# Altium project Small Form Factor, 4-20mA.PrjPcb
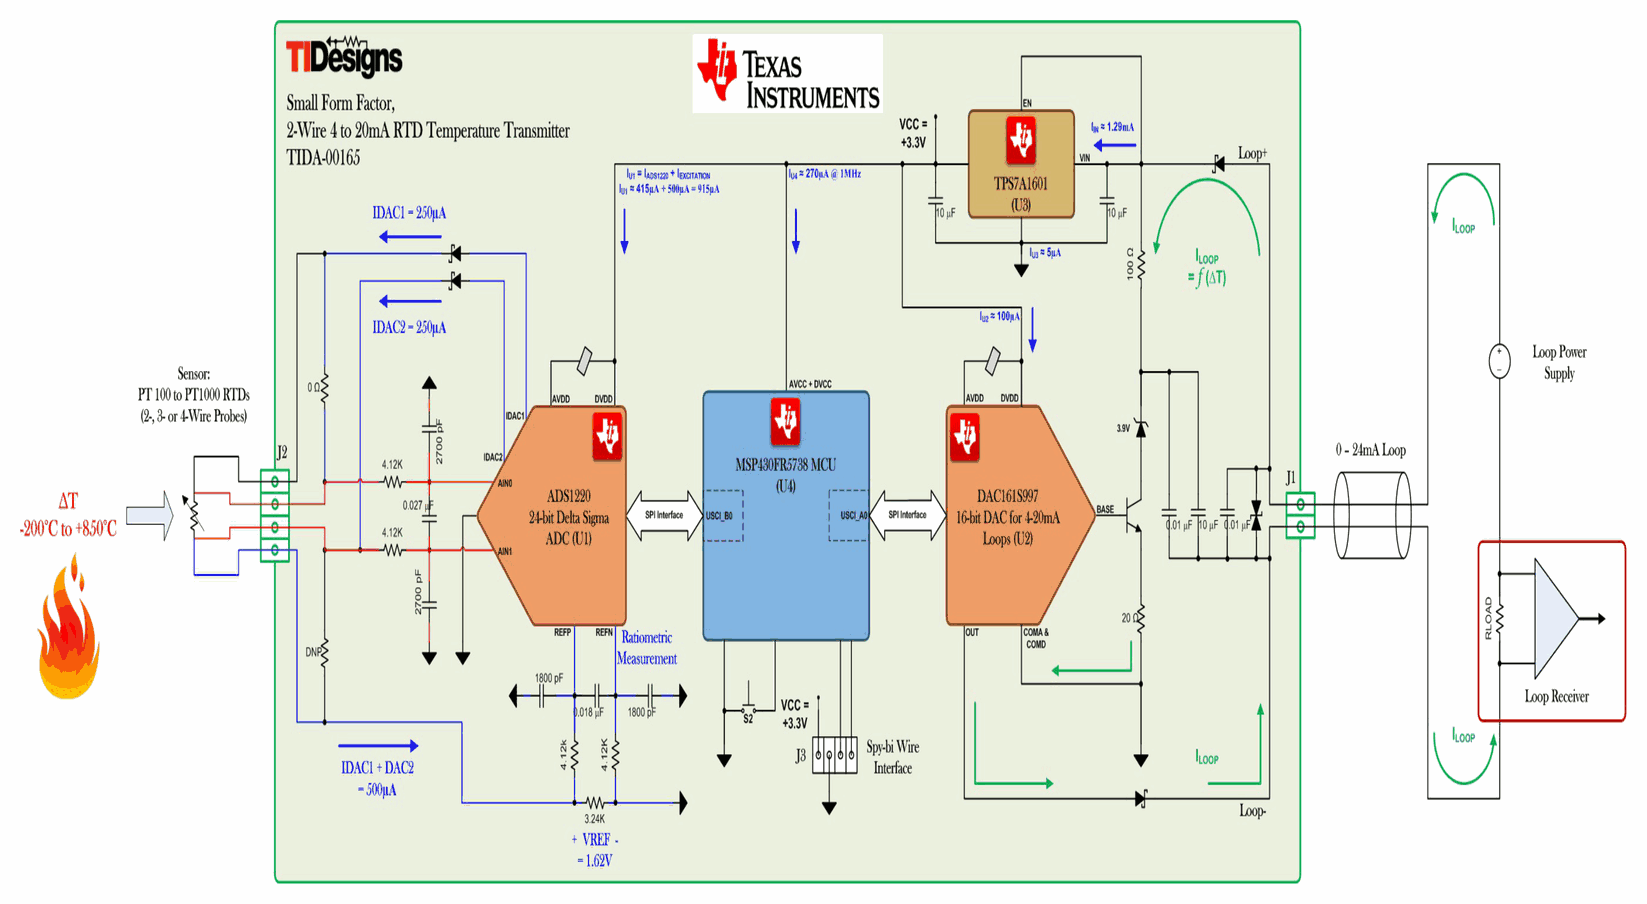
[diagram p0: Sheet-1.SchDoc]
CopyrightYear: 2014; PCB_Layout: Who did the Layout?; PCB_Rev: E1; PRJ_Customer: Public Release; PRJ_Engineer: Sharad Yadav; PRJ_Number: TIDA-00165; PRJ_Title: Small Form Factor 4-20mA Temperature Transmitter; SCH_Rev: E1; TechSupport: http://www.ti.com/support
4 sheets, 68 parts. Net scope: global (net labels, ports and power ports of the same name join across sheets).
Board file: TIDA-00165.PcbDoc
Sheets:
  Sheet-1.SchDoc
  Sheet-2.SchDoc
  Sheet-3.SchDoc
  Sheet-4.SchDoc

## Sheet Sheet-1.SchDoc
size 431 x 279 mm; Date: Not shown in title block; ApprovedBy: Not shown in title block; CheckedBy: Not shown in title block; Author: Not shown in title block; CompanyName: Not shown in title block; Engineer: Not shown in title block; Organization: Not shown in title block; Address1: Not shown in title block; Address2: Not shown in title block; Address3: Not shown in title block; Address4: Not shown in title block; DocumentNumber: 1; Revision: Use project parameter SCH_Rev; SheetNumber: 1; SheetTotal: 4; PageSetup: Record=PageOptions|CenterHorizontal=True|CenterVertical=True|PrintScale=1.00|XCorrection=1.00|YCorrection=1.00|PrintKind=0|BorderSize=5000000|LeftOffset=0|BottomOffset=0|Orientation=2|PaperLength=1000|PaperWidth=1000|Scale=100|PaperSource=15|PrintQuality=600|MediaType=1|DitherType=10|PaperKind=Letter|PrintScaleMode=1

## Sheet Sheet-2.SchDoc
size 431 x 279 mm; Date: Not shown in title block; ApprovedBy: Not shown in title block; CheckedBy: Not shown in title block; Author: Not shown in title block; CompanyName: Not shown in title block; Engineer: Not shown in title block; Organization: Not shown in title block; Address1: Not shown in title block; Address2: Not shown in title block; Address3: Not shown in title block; Address4: Not shown in title block; DocumentNumber: 2; Revision: Use project parameter SCH_Rev; SheetNumber: 2; SheetTotal: 4; PageSetup: Record=PageOptions|CenterHorizontal=True|CenterVertical=True|PrintScale=1.00|XCorrection=1.00|YCorrection=1.00|PrintKind=0|BorderSize=5000000|LeftOffset=0|BottomOffset=0|Orientation=2|PaperLength=1000|PaperWidth=1000|Scale=100|PaperSource=15|PrintQuality=600|MediaType=1|DitherType=10|PaperKind=Letter|PrintScaleMode=1
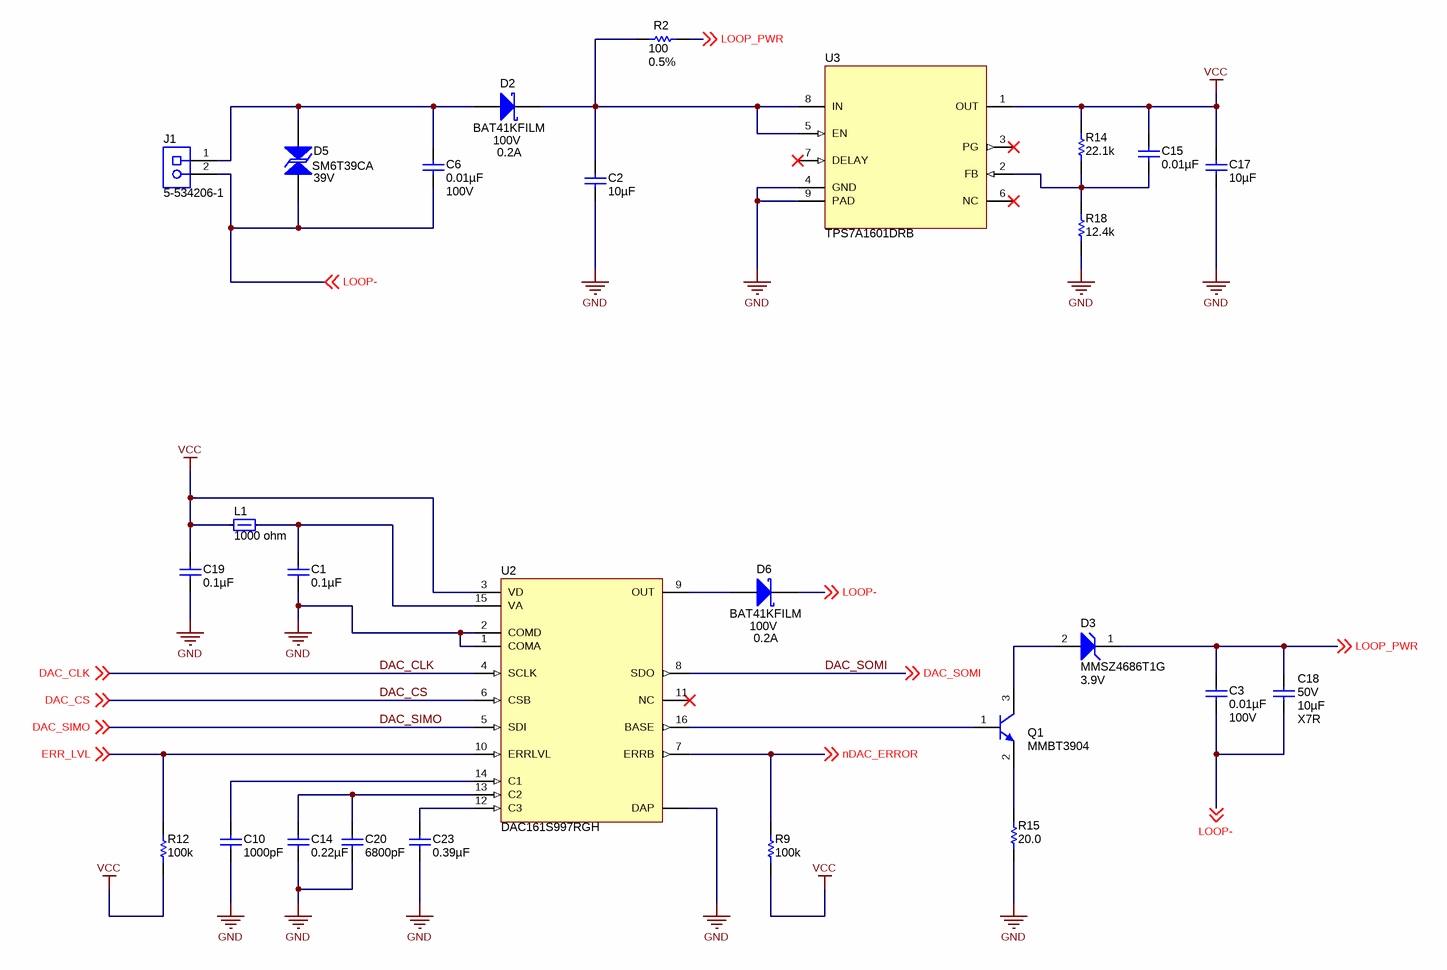
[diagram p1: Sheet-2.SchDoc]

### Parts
C1  ValueDisplayed: 0.1µF  [0402]  (hidden comment: C1005X5R0J104K)
C2  ValueDisplayed: 10µF  [1210]  (hidden comment: GRM32ER71H106KA12L)
C3  ValueDisplayed: 0.01µF  Value2: 100V  [0603]  (hidden comment: C1608X7R2A103K)
C6  ValueDisplayed: 0.01µF  Value2: 100V  [0603]  (hidden comment: C1608X7R2A103K)
C10  ValueDisplayed: 1000pF  [0402]  (hidden comment: GRM155R60J102KA01D)
C14  ValueDisplayed: 0.22µF  [0402]  (hidden comment: GRM155R60J224KE01D)
C15  ValueDisplayed: 0.01µF  [0402]  (hidden comment: GRM155R70J103KA01D)
C17  ValueDisplayed: 10µF  [0805_HV]  (hidden comment: GRM21BR70J106KE76L)
C18  ValueDisplayed: 10µF  Value2: 50V  TempCo: X7R  [1210]  (hidden comment: GRM32ER71H106KA12L)
C19  ValueDisplayed: 0.1µF  [0402]  (hidden comment: C1005X5R0J104K)
C20  ValueDisplayed: 6800pF  [0402]  (hidden comment: GRM155R71E682KA01D)
C23  ValueDisplayed: 0.39µF  [0402]  (hidden comment: GRM155R61A394KE15D)
D2  BAT41KFILM  value 100V  Value1: 0.2A  [SOD-523]
D3  MMSZ4686T1G  value 3.9V  [SOD-123]
D5  value 39V  [SMB]  (hidden comment: SM6T39CA)
D6  BAT41KFILM  value 100V  Value1: 0.2A  [SOD-523]
J1  5-534206-1  [CONN_534206-1]
L1  value 1000 ohm  [0402]  (hidden comment: BLM15HG102SN1D)
Q1  MMBT3904  [SOT-23]
R2  value 100  Value1: 0.5%  [0603]  (hidden comment: RT0603DRE07100RL)
R9  value 100k  [0402]  (hidden comment: CRCW0402100KJNED)
R12  value 100k  [0402]  (hidden comment: CRCW0402100KJNED)
R14  value 22.1k  [0402]  (hidden comment: CRCW040222K1FKED)
R15  value 20.0  [0402]  (hidden comment: CRCW040220R0FKED)
R18  value 12.4k  [0402]  (hidden comment: CRCW040212K4FKED)
U2  DAC161S997RGH  [RGH0016A]
U3  TPS7A1601DRB  [DRB0008A]

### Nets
GND: C1.2 C2.2 C10.2 C14.2 C17.2 C19.2 C20.2 C23.2 R15.2 R18.1 U2.1(COMA) U2.2(COMD) U2.17(DAP) U3.4(GND) U3.9(PAD)
VCC: C15.1 C17.1 C19.1 L1.1 R9.1 R12.2 R14.2 U2.3(VD) U3.1(OUT)
DAC_CLK: U2.4(SCLK) ; off-sheet DAC_CLK
DAC_CS: U2.6(CSB) ; off-sheet DAC_CS
DAC_SIMO: U2.5(SDI) ; off-sheet DAC_SIMO
DAC_SOMI: U2.8(SDO) ; off-sheet DAC_SOMI
ERR_LVL: R12.1 U2.10(ERRLVL) ; off-sheet ERR_LVL
LOOP-: C3.2 C6.2 C18.2 D5.2 D6.1(K) J1.2 ; off-sheet LOOP-
LOOP_PWR: C3.1 C18.1 D3.1(K) R2.2 ; off-sheet LOOP_PWR
nDAC_ERROR: R9.2 U2.7(ERRB) ; off-sheet nDAC_ERROR
NetC1_1: C1.1 L1.2 U2.15(VA)
NetC2_1: C2.1 D2.1(K) R2.1 U3.5(EN) U3.8(IN)
NetC6_1: C6.1 D2.2(A) D5.1 J1.1
NetC10_1: C10.1 U2.14(C1)
NetC14_1: C14.1 C20.1 U2.13(C2)
NetC15_2: C15.2 R14.1 R18.2 U3.2(FB)
NetC23_1: C23.1 U2.12(C3)
NetD3_2: D3.2(A) Q1.3(C)
NetD6_2: D6.2(A) U2.9(OUT)
NetQ1_1: Q1.1(B) U2.16(BASE)
NetQ1_2: Q1.2(E) R15.1

Not connected (* = marked no-connect by the designer): U2 11(NC)*; U3 3(PG)* 6(NC)* 7(DELAY)*

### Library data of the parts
C1 C19 = C1005X5R0J104K: CAP, CERM, 0.1uF, 6.3V, +/-10%, X5R, 0402; Manufacturer: TDK; Polarized: N; CompType: Capacitor; U/M: EA; Cap_F: 0.0000001; Tolerance_%: 10; ESR_Ohm: 0.0186; Value1: 0.0186 ohm; VDC_V: 6.3; TaMin_C: -55; TaMax_C: 85
C2 C18 = GRM32ER71H106KA12L: CAP, CERM, 10uF, 50V, +/-10%, X7R, 1210; Manufacturer: MuRata; Polarized: N; CompType: Capacitor; U/M: EA; Cap_F: 0.00001; Tolerance_%: 10; Value1: Unknown; VDC_V: 50; TaMin_C: -55; TaMax_C: 125
C3 C6 = C1608X7R2A103K: CAP, CERM, 0.01uF, 100V, +/-10%, X7R, 0603; Manufacturer: TDK; Polarized: N; CompType: Capacitor; U/M: EA; Cap_F: 0.00000001; Tolerance_%: 10; ESR_Ohm: 0.0661; Value1: 0.0661 ohm; VDC_V: 100; TaMin_C: -55; TaMax_C: 125
C10 = GRM155R60J102KA01D: CAP, CERM, 1000pF, 6.3V, +/-10%, X5R, 0402; Manufacturer: MuRata; Polarized: N; CompType: Capacitor; U/M: EA; Cap_F: 0.000000001; Tolerance_%: 10; Value1: Unknown; VDC_V: 6.3; TaMin_C: -55; TaMax_C: 85
C14 = GRM155R60J224KE01D: CAP, CERM, 0.22uF, 6.3V, +/-10%, X5R, 0402; Manufacturer: MuRata; Polarized: N; CompType: Capacitor; U/M: EA; Cap_F: 0.00000022; Tolerance_%: 10; Value1: Unknown; VDC_V: 6.3; TaMin_C: -55; TaMax_C: 85
C15 = GRM155R70J103KA01D: CAP, CERM, 0.01uF, 6.3V, +/-10%, X7R, 0402; Manufacturer: MuRata; Polarized: N; CompType: Capacitor; U/M: EA; Cap_F: 0.00000001; Tolerance_%: 10; Value1: Unknown; VDC_V: 6.3; TaMin_C: -55; TaMax_C: 125
C17 = GRM21BR70J106KE76L: CAP, CERM, 10uF, 6.3V, +/-10%, X7R, 0805; Manufacturer: MuRata; Polarized: N; CompType: Capacitor; U/M: EA; Cap_F: 0.00001; Tolerance_%: 10; Value1: Unknown; VDC_V: 6.3; TaMin_C: -55; TaMax_C: 125; Cap_Case: 0805
C20 = GRM155R71E682KA01D: CAP, CERM, 6800pF, 25V, +/-10%, X7R, 0402; Manufacturer: MuRata; Polarized: N; CompType: Capacitor; U/M: EA; Cap_F: 0.0000000068; Tolerance_%: 10; Value1: Unknown; VDC_V: 25; TaMin_C: -55; TaMax_C: 125
C23 = GRM155R61A394KE15D: CAP, CERM, 0.39uF, 10V, +/-10%, X5R, 0402; Manufacturer: MuRata; Polarized: N; CompType: Capacitor; U/M: EA; Cap_F: 0.00000039; Tolerance_%: 10; Value1: Unknown; TaMin_C: -55; TaMax_C: 85
D2 D6 = BAT41ZFILM: DIODE SCHOTTKY 100V 0.2A SOD523; Manufacturer: ST Microelectronics; U/M: EA; Vf_V: 1; Value2: 1V; Io_A: 0.2; Vr_V: 100; TJmax_C: 150
D3 = MMSZ4686T1G: Diode, Zener, 3.9V, 500mW, SOD-123; Manufacturer: ON Semiconductor; U/M: EA; Power_W: 0.5; Vz_V: 3.9; Value1: 0.5W; RJA_CperW: 340
D5 = SMBJ40CA-13-F: TVS DIODE 33.3VWM 69.7VC SMB; Manufacturer: STMicroelectronics; U/M: EA; Power_W: 600; Value1: 600W
J1 = 5-534206-1: Connector, Receptacle, 100mil, 2x1, Gold plated, TH; Manufacturer: TE Connectivity; SymbolCreator: a0412235; U/M: EA
L1 = BLM15HG102SN1D: 0.25A Ferrite Bead, 1000 ohm @ 100MHz, SMD; Manufacturer: MuRata; Imax_A: 0.25; Irms: 0.25A @ C rise; Isat: 0.25A @ % inductance drop; DCR_ohm: 1.1; Value1: 1.1 ohm; ZTyp@100MHz_Ohm: 1000; U/M: EA
Q1 = MMBT3904, Fairchild Semiconductor: Transistor, NPN, 40V, 0.2A, SOT-23; CompType: BJT; PNP: 0; NPN: 1; Vceo_V: 40; Vcesat1_V: 0.2; Value: 0.2V; HfeMax: 300; TaMin_C: -55; TaMax_C: 150; U/M: EA
R2 = RT0603DRE07100RL: RES, 100 ohm, 0.5%, 0.1W, 0603; Manufacturer: Yageo America; CompType: Resistor; Value_Code: 100R; Tolerance_%: 0.5; Power_W: 0.1; VDC_V: 75; TempCo: 50 ppm/C; EIA_Code: E192; U/M: EA
R9 R12 = CRCW0402100KJNED: RES, 100k ohm, 5%, 0.063W, 0402; Manufacturer: Vishay-Dale; CompType: Resistor; Res_ohm: 100000; Tolerance_%: 5; Power_W: 0.063; VDC_V: 50; TempCo: 200 ppm/C; EIA_Code: E24; U/M: EA
R14 = CRCW040222K1FKED: RES, 22.1k ohm, 1%, 0.063W, 0402; Manufacturer: Vishay-Dale; CompType: Resistor; Res_ohm: 22100; Value_Code: 22k1; Tolerance_%: 1; Power_W: 0.063; VDC_V: 50; TempCo: 100 ppm/C; EIA_Code: E96; U/M: EA
R15 = CRCW040220R0FKED: RES, 20.0 ohm, 1%, 0.063W, 0402; Manufacturer: Vishay-Dale; CompType: Resistor; Res_ohm: 20; Value_Code: 20R0; Tolerance_%: 1; Power_W: 0.063; VDC_V: 50; TempCo: 100 ppm/C; EIA_Code: E96; U/M: EA
R18 = CRCW040212K4FKED: RES, 12.4k ohm, 1%, 0.063W, 0402; Manufacturer: Vishay-Dale; CompType: Resistor; Res_ohm: 12400; Value_Code: 12k4; Tolerance_%: 1; Power_W: 0.063; VDC_V: 50; TempCo: 100 ppm/C; EIA_Code: E96; U/M: EA
U2 = DAC161S997RGH: 16-bit SPI Programmable DAC for 4-20mA Loops, RGH0016A; Alternate Manufacturer: None; Manufacturer: Texas Instruments; SymbolCreator: x0208325; CompType: IC; U/M: EA
U3 = TPS7A1601DRB: 60-V, 5-µA IQ, 100-mA, Low-Dropout Voltage Regulator with Enable and Power-Good, DRB0008A; Alternate Manufacturer: None; Manufacturer: Texas Instruments; SymbolCreator: a0411947; CompType: IC; U/M: EA

## Sheet Sheet-3.SchDoc
size 431 x 279 mm; Date: Not shown in title block; ApprovedBy: Not shown in title block; CheckedBy: Not shown in title block; Author: Not shown in title block; CompanyName: Not shown in title block; Engineer: Not shown in title block; Organization: Not shown in title block; Address1: Not shown in title block; Address2: Not shown in title block; Address3: Not shown in title block; Address4: Not shown in title block; DocumentNumber: 3; Revision: Use project parameter SCH_Rev; SheetNumber: 3; SheetTotal: 4; PageSetup: Record=PageOptions|CenterHorizontal=True|CenterVertical=True|PrintScale=1.00|XCorrection=1.00|YCorrection=1.00|PrintKind=0|BorderSize=5000000|LeftOffset=0|BottomOffset=0|Orientation=2|PaperLength=1000|PaperWidth=1000|Scale=100|PaperSource=15|PrintQuality=600|MediaType=1|DitherType=10|PaperKind=Letter|PrintScaleMode=1
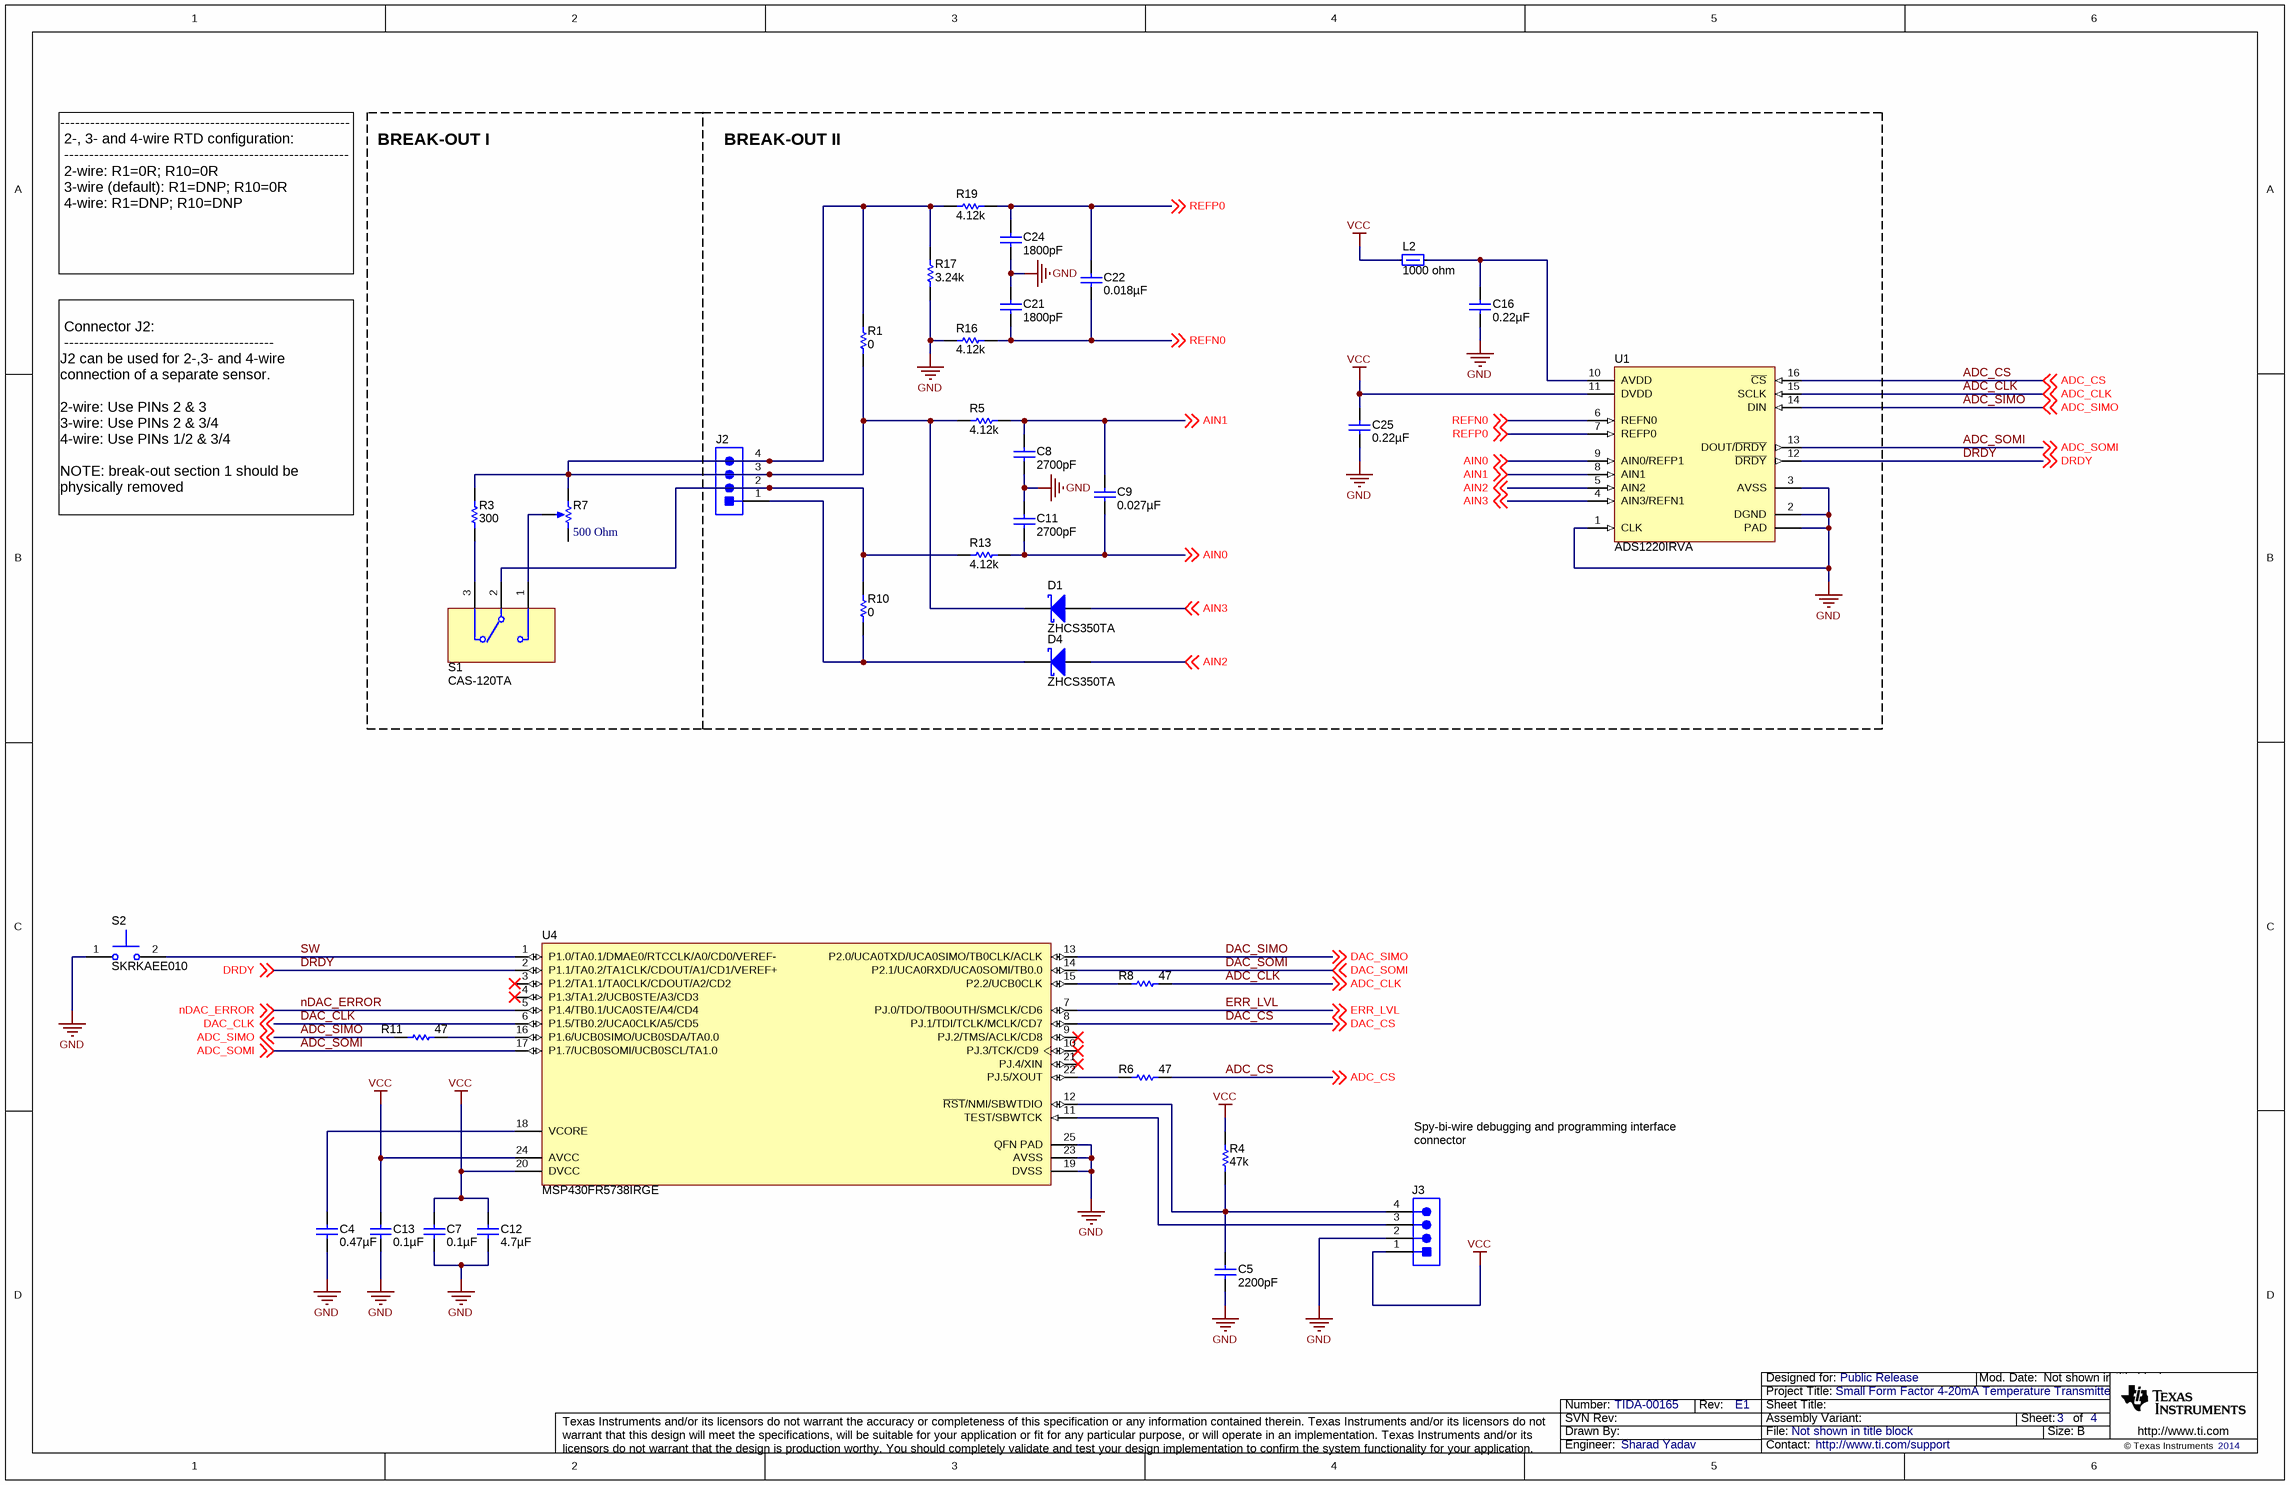
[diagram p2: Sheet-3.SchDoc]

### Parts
C4  ValueDisplayed: 0.47µF  [0402]  (hidden comment: GRM155R60J474KE19D)
C5  ValueDisplayed: 2200pF  [0402]  (hidden comment: GRM155R70J222KA01D)
C7  ValueDisplayed: 0.1µF  [0402]  (hidden comment: C1005X5R0J104K)
C8  ValueDisplayed: 2700pF  [0402S]  (hidden comment: GRM155R72A272KA01D)
C9  ValueDisplayed: 0.027µF  [0603S]  (hidden comment: C0603C273K1RACTU)
C11  ValueDisplayed: 2700pF  [0402S]  (hidden comment: GRM155R72A272KA01D)
C12  ValueDisplayed: 4.7µF  [0402]  (hidden comment: C1005X5R0J475M050BC)
C13  ValueDisplayed: 0.1µF  [0402]  (hidden comment: C1005X5R0J104K)
C16  ValueDisplayed: 0.22µF  [0402]  (hidden comment: GRM155R60J224KE01D)
C21  ValueDisplayed: 1800pF  [0402S]  (hidden comment: GRM155R72A182KA01D)
C22  ValueDisplayed: 0.018µF  [0603S]  (hidden comment: C0603C183K1RACTU)
C24  ValueDisplayed: 1800pF  [0402S]  (hidden comment: GRM155R72A182KA01D)
C25  ValueDisplayed: 0.22µF  [0402]  (hidden comment: GRM155R60J224KE01D)
D1  ZHCS350TA  [SOD-523]
D4  ZHCS350TA  [SOD-523]
J2  850-10-004-20-001000  [Mill-Max_850-10-004-20-001000]  (value not drawn)
J3  850-10-004-40-001000  [Mill-max_850-10-004-40-001000]  (value not drawn)
L2  value 1000 ohm  [0402]  (hidden comment: BLM15HG102SN1D)
R1  value 0  [0402]  (hidden comment: CRCW04020000Z0ED)
R3  value 300  [0603S]  (hidden comment: RG1608P-301-B-T5)
R4  value 47k  [0402]  (hidden comment: CRCW040247K0JNED)
R5  value 4.12k  [0603S]  (hidden comment: RG1608P-4121-B-T5)
R6  value 47  [0402]  (hidden comment: CRCW040247R0JNED)
R7  value 500 Ohm  [Bourns_3223W]  (hidden comment: 3223W-1-501E)
R8  value 47  [0402]  (hidden comment: CRCW040247R0JNED)
R10  value 0  [0402]  (hidden comment: CRCW04020000Z0ED)
R11  value 47  [0402]  (hidden comment: CRCW040247R0JNED)
R13  value 4.12k  [0603S]  (hidden comment: RG1608P-4121-B-T5)
R16  value 4.12k  [0603S]  (hidden comment: RG1608P-4121-B-T5)
R17  value 3.24k  [1206L]  (hidden comment: PFC-W1206R-12-3241-B)
R19  value 4.12k  [0603S]  (hidden comment: RG1608P-4121-B-T5)
S1  CAS-120TA  [SW_CAS-120TA]
S2  SKRKAEE010  [SW_SKRKAEE010]
U1  ADS1220IRVA  [RVA0016A]
U4  MSP430FR5738IRGE  [RGE0024G]

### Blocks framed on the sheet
BREAK-OUT I: R3 R7 S1

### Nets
GND: C4.2 C5.2 C7.2 C8.2 C11.1 C12.2 C13.2 C16.2 C21.1 C24.2 C25.2 J3.2 R16.1 R17.1 S2.1 U1.1(CLK) U1.2(DGND) U1.3(AVSS) U1.17(PAD) U4.19(DVSS) U4.23(AVSS) U4.25(QFN_PAD)
VCC: C7.1 C12.1 C13.1 C25.1 J3.1 L2.1 R4.2 U1.11(DVDD) U4.20(DVCC) U4.24(AVCC)
ADC_CLK: R8.2 U1.15(SCLK) ; off-sheet ADC_CLK
ADC_CS: R6.2 U1.16(~{CS}) ; off-sheet ADC_CS
ADC_SIMO: R11.1 U1.14(DIN) ; off-sheet ADC_SIMO
ADC_SOMI: U1.13(DOUT/~{DRDY}) U4.17(P1.7/UCB0SOMI/UCB0SCL/TA1.0) ; off-sheet ADC_SOMI
AIN0: C9.2 C11.2 R13.2 U1.9(AIN0/REFP1) ; off-sheet AIN0
AIN1: C8.1 C9.1 R5.2 U1.8(AIN1) ; off-sheet AIN1
AIN2: D4.2(A) U1.5(AIN2) ; off-sheet AIN2
AIN3: D1.2(A) U1.4(AIN3/REFN1) ; off-sheet AIN3
DAC_CLK: U4.6(P1.5/TB0.2/UCA0CLK/A5/CD5) ; off-sheet DAC_CLK
DAC_CS: U4.8(PJ.1/TDI/TCLK/MCLK/CD7) ; off-sheet DAC_CS
DAC_SIMO: U4.13(P2.0/UCA0TXD/UCA0SIMO/TB0CLK/ACLK) ; off-sheet DAC_SIMO
DAC_SOMI: U4.14(P2.1/UCA0RXD/UCA0SOMI/TB0.0) ; off-sheet DAC_SOMI
DRDY: U1.12(~{DRDY}) U4.2(P1.1/TA0.2/TA1CLK/CDOUT/A1/CD1/VEREF+) ; off-sheet DRDY
ERR_LVL: U4.7(PJ.0/TDO/TB0OUTH/SMCLK/CD6) ; off-sheet ERR_LVL
nDAC_ERROR: U4.5(P1.4/TB0.1/UCA0STE/A4/CD4) ; off-sheet nDAC_ERROR
REFN0: C21.2 C22.2 R16.2 U1.6(REFN0) ; off-sheet REFN0
REFP0: C22.1 C24.1 R19.2 U1.7(REFP0) ; off-sheet REFP0
SW: S2.2 U4.1(P1.0/TA0.1/DMAE0/RTCCLK/A0/CD0/VEREF-)
NetC4_1: C4.1 U4.18(VCORE)
NetC5_1: C5.1 J3.4 R4.1 U4.12(~{RST}/NMI/SBWTDIO)
NetC16_1: C16.1 L2.2 U1.10(AVDD)
NetD1_1: D1.1(K) J2.3 J2.4 R1.1 R1.2 R3.2 R5.1 R7.1(CCW) R17.2 R19.1
NetD4_1: D4.1(K) J2.1 R10.1
NetJ2_2: J2.2 R10.2 R13.1 S1.2
NetJ3_3: J3.3 U4.11(TEST/SBWTCK)
NetR3_1: R3.1 S1.3
NetR6_1: R6.1 U4.22(PJ.5/XOUT)
NetR7_2: R7.2(WIPER) S1.1
NetR8_1: R8.1 U4.15(P2.2/UCB0CLK)
NetR11_2: R11.2 U4.16(P1.6/UCB0SIMO/UCB0SDA/TA0.0)

Not connected (* = marked no-connect by the designer): R7 3(CW); U4 3(P1.2/TA1.1/TA0CLK/CDOUT/A2/CD2)* 4(P1.3/TA1.2/UCB0STE/A3/CD3)* 9(PJ.2/TMS/ACLK/CD8)* 10(PJ.3/TCK/CD9)* 21(PJ.4/XIN)*

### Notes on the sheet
- BREAK-OUT II
- ----------------------------------------------------------
  2-, 3- and 4-wire RTD configuration:
  ---------------------------------------------------------
  2-wire: R1=0R; R10=0R
  3-wire (default): R1=DNP; R10=0R
  4-wire: R1=DNP; R10=DNP
- Connector J2:
  ------------------------------------------
  J2 can be used for 2-,3- and 4-wire connection of a separate sensor.
  2-wire: Use PINs 2 & 3
  3-wire: Use PINs 2 & 3/4
  4-wire: Use PINs 1/2 & 3/4
  NOTE: break-out section 1 should be physically removed
- (near J3) Spy-bi-wire debugging and programming interface
  connector

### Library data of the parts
C4 = GRM155R60J474KE19D: CAP, CERM, 0.47uF, 6.3V, +/-10%, X5R, 0402; Manufacturer: MuRata; Polarized: N; CompType: Capacitor; U/M: EA; Cap_F: 0.00000047; Tolerance_%: 10; Value1: Unknown; VDC_V: 6.3; TaMin_C: -55; TaMax_C: 85
C5 = GRM155R70J222KA01D: CAP, CERM, 2200pF, 6.3V, +/-10%, X7R, 0402; Manufacturer: MuRata; Polarized: N; CompType: Capacitor; U/M: EA; Cap_F: 0.0000000022; Tolerance_%: 10; Value1: Unknown; VDC_V: 6.3; TaMin_C: -55; TaMax_C: 125
C7 C13 = C1005X5R0J104K: as C1 on sheet Sheet-2
C8 C11 = GRM155R72A272KA01D: CAP, CERM, 2700pF, 100V, +/-10%, X7R, 0402; Manufacturer: MuRata; Polarized: N; CompType: Capacitor; U/M: EA; Cap_F: 0.0000000027; Tolerance_%: 10; Value1: Unknown; VDC_V: 100; TaMin_C: -55; TaMax_C: 125; Cap_Case: 0402
C9 = C0603C273K1RACTU: CAP, CERM, 0.027uF, 100V, +/-10%, X7R, 0603; Manufacturer: Kemet; Polarized: N; CompType: Capacitor; U/M: EA; Cap_F: 0.000000027; Tolerance_%: 10; Value1: Unknown; VDC_V: 100; TaMin_C: -55; TaMax_C: 125; Cap_Case: 0603
C12 = C1005X5R0J475M050BC: CAP, CERM, 4.7uF, 6.3V, +/-20%, X5R, 0402; Manufacturer: TDK; Polarized: N; CompType: Capacitor; U/M: EA; Cap_F: 0.0000047; Tolerance_%: 20; Value1: Unknown; VDC_V: 6.3; TaMin_C: -55; TaMax_C: 85
C16 C25 = GRM155R60J224KE01D: as C14 on sheet Sheet-2
C21 C24 = GRM155R72A182KA01D: CAP, CERM, 1800pF, 100V, +/-10%, X7R, 0402; Manufacturer: MuRata; Polarized: N; CompType: Capacitor; U/M: EA; Cap_F: 0.0000000018; Tolerance_%: 10; Value1: Unknown; VDC_V: 100; TaMin_C: -55; TaMax_C: 125; Cap_Case: 0402
C22 = C0603C183K1RACTU: CAP, CERM, 0.018uF, 100V, +/-10%, X7R, 0603; Manufacturer: Kemet; Polarized: N; CompType: Capacitor; U/M: EA; Cap_F: 0.000000018; Tolerance_%: 10; Value1: Unknown; VDC_V: 100; TaMin_C: -55; TaMax_C: 125; Cap_Case: 0603
D1 D4 = ZHCS350TA: Diode, Schottky, 40V, 0.35A, SOD-523; Manufacturer: Diodes Inc.; U/M: EA; Vf_V: 0.65; Value2: 0.65V; Io_A: 0.35; Vr_V: 40
J2 = 850-10-004-20-001000: Header, 4x1, 50mil, R/A, TH; Manufacturer: Mill-Max; SymbolCreator: a0412235; U/M: EA
J3 = 850-10-004-40-001000: Header, 4x1, 50mil, R/A, SMT; Manufacturer: Mill-Max; SymbolCreator: a0412235; U/M: EA
L2 = BLM15HG102SN1D: as L1 on sheet Sheet-2
R1 R10 = CRCW04020000Z0ED: RES, 0 ohm, 5%, 0.063W, 0402; Manufacturer: Vishay-Dale; CompType: Resistor; Value_Code: 0000; Tolerance_%: 5; Power_W: 0.063; VDC_V: 50; TempCo: 200 ppm/C; EIA_Code: E24; U/M: EA
R3 = RG1608P-301-B-T5: RES, 300 ohm, 0.1%, 0.1W, 0603; Manufacturer: Susumu Co Ltd; CompType: Resistor; Value_Code: 300R; Tolerance_%: 0.1; VDC_V: 75; TempCo: 25 ppm/C; U/M: EA
R4 = CRCW040247K0JNED: RES, 47k ohm, 5%, 0.063W, 0402; Manufacturer: Vishay-Dale; CompType: Resistor; Res_ohm: 47000; Value_Code: 47k0; Tolerance_%: 5; Power_W: 0.063; VDC_V: 50; TempCo: 200 ppm/C; EIA_Code: E24; U/M: EA
R5 R13 R16 R19 = RG1608P-4121-B-T5: RES, 4.12k ohm, 0.1%, 0.1W, 0603; Manufacturer: Susumu Co Ltd; CompType: Resistor; Res_ohm: 4120; Value_Code: 4k12; Tolerance_%: 0.1; VDC_V: 75; TempCo: 25 ppm/C; EIA_Code: E192; U/M: EA
R6 R8 R11 = CRCW040247R0JNED: RES, 47 ohm, 5%, 0.063W, 0402; Manufacturer: Vishay-Dale; CompType: Resistor; Value_Code: 47R0; Tolerance_%: 5; Power_W: 0.063; VDC_V: 50; TempCo: 200 ppm/C; EIA_Code: E24; U/M: EA
R7 = 3223W-1-501E: TRIMMER 500 OHM 0.125W SMD; Manufacturer: Bourns; Sim Note: Enter the Resistance value and the set point into parameter fields.; SymbolCreator: a0412235
R17 = PFC-W1206R-12-3241-B: RES, 3.24k ohm, 0.1%, 0.333W, 1206; Manufacturer: TT Electronics/IRC; CompType: Resistor; Res_ohm: 3240; Value_Code: 3k24; Tolerance_%: 0.1; Power_W: 0.333; TempCo: 10 ppm/C; EIA_Code: E192; U/M: EA
S1 = CAS-120TA: Switch, Slide, SPDT  100mA, SMT; Manufacturer: Copal Electronics; SymbolCreator: a0411947; VDC_V: 6; SwitchFunction: On-On; PositionCount: 1; CurrentRating_mA: 100
S2 = SKRKAEE010: Switch, Push Button, SMD; Manufacturer: Alps; SymbolCreator: a0412235; Circuit: SPST-NO; VDC_V: 12; SwitchFunction: Off-Mom; PositionCount: 1; CurrentRating_mA: 50
U1 = ADS1220IRVA: Low-Power, Low-Noise, 24-Bit Analog-to-Digital Converter for Small Signal Sensors, RVA0016A; Alternate Manufacturer: None; Manufacturer: Texas Instruments; SymbolCreator: x0208326; CompType: IC; U/M: EA
U4 = MSP430FR5738IRGE: 24 MHz Mixed Signal Microcontroller, 1024 B SRAM and 17 GPIOs, -40 to 85 degC, RGE0024G; Manufacturer: Texas Instruments; Alternate Manufacturer: None; ADC: 10-bit SAR; ADC Channels: 10; Brown Out Reset: Yes; DMA: 3; Eco-Plan: Green (RoHS & no Sb/Br); FRAM(KB): 16; Frequency(MHz): 24; GPIO: 17; Multiplier: 32x32; SRAM(B): 1024; SubFamily: FRAM Series; USCI_A (UART/LIN/IrDA/SPI): 1; SymbolCreator: Altium; CompType: IC; U/M: EA

## Sheet Sheet-4.SchDoc
size 431 x 279 mm; Date: Not shown in title block; ApprovedBy: Not shown in title block; CheckedBy: Not shown in title block; Author: Not shown in title block; CompanyName: Not shown in title block; Engineer: Not shown in title block; Organization: Not shown in title block; Address1: Not shown in title block; Address2: Not shown in title block; Address3: Not shown in title block; Address4: Not shown in title block; DocumentNumber: 4; Revision: Use project parameter SCH_Rev; SheetNumber: 4; SheetTotal: 4; PageSetup: Record=PageOptions|CenterHorizontal=True|CenterVertical=True|PrintScale=1.00|XCorrection=1.00|YCorrection=1.00|PrintKind=0|BorderSize=5000000|LeftOffset=0|BottomOffset=0|Orientation=2|PaperLength=1000|PaperWidth=1000|Scale=100|PaperSource=15|PrintQuality=600|MediaType=1|DitherType=10|PaperKind=Letter|PrintScaleMode=1
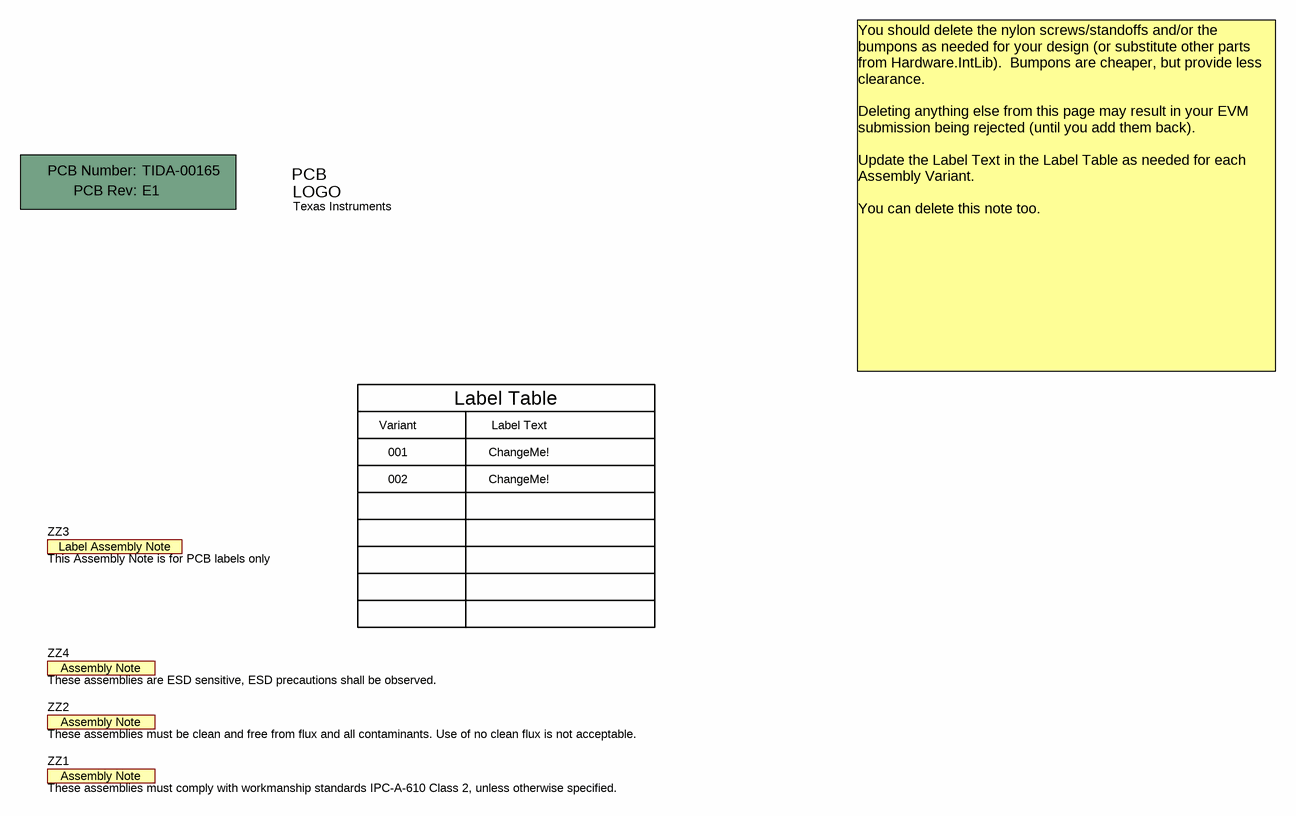
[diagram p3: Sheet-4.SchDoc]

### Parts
!PCB1  Printed Circuit Board  (value not drawn)  (mechanical)
Logo1  Texas Instruments  [TI_Symbol_Overlay_Small]  (no BOM)
ZZ1  These assemblies must comply with workmanship standards IPC-A-610 Class 2, unless otherwise specified.  [AssemblyNote]  (no BOM)
ZZ2  These assemblies must be clean and free from flux and all contaminants. Use of no clean flux is not acceptable.  [AssemblyNote]  (no BOM)
ZZ3  This Assembly Note is for PCB labels only  [AssemblyNoteLabel]  (no BOM)
ZZ4  These assemblies are ESD sensitive, ESD precautions shall be observed.  [AssemblyNote]  (no BOM)

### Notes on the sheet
- Variant
- Label Table
- Label Text
- You should delete the nylon screws/standoffs and/or the bumpons as needed for your design (or substitute other parts from Hardware.IntLib).  Bumpons are cheaper, but provide less clearance.
  Deleting anything else from this page may result in your EVM submission being rejected (until you add them back).
  Update the Label Text in the Label Table as needed for each Assembly Variant.
  You can delete this note too.
- 001
- 002
- ChangeMe!

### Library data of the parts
!PCB1 = PCB: Manufacturer: Any; PartNumber: TIDA-00165; SymbolCreator: a0412235
Logo1 = TI_Logo: Texas Instrument Corporate Signature; SymbolCreator: codlsc
ZZ1 ZZ2 ZZ4 = AssemblyNote: SymbolCreator: codlsc
ZZ3 = AssemblyNoteLabel: SymbolCreator: a0412235

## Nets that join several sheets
GND: Sheet-2 (15 pins), Sheet-3 (22 pins)
VCC: Sheet-2 (9 pins), Sheet-3 (10 pins)
DAC_CLK: Sheet-2 (U2.4), Sheet-3 (U4.6)
DAC_CS: Sheet-2 (U2.6), Sheet-3 (U4.8)
DAC_SIMO: Sheet-2 (U2.5), Sheet-3 (U4.13)
DAC_SOMI: Sheet-2 (U2.8), Sheet-3 (U4.14)
ERR_LVL: Sheet-2 (R12.1 U2.10), Sheet-3 (U4.7)
nDAC_ERROR: Sheet-2 (R9.2 U2.7), Sheet-3 (U4.5)

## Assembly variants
001: not fitted FID1 FID2 FID3 R9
